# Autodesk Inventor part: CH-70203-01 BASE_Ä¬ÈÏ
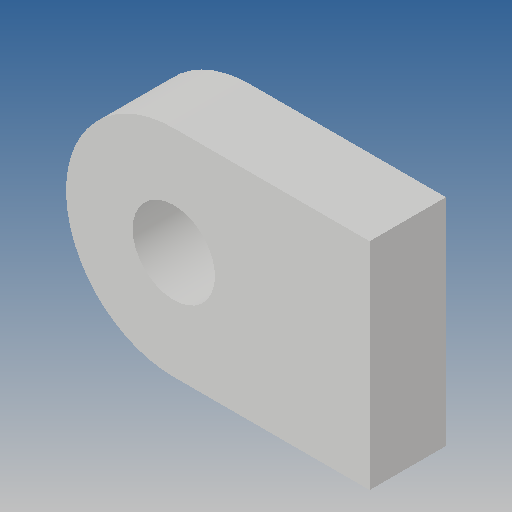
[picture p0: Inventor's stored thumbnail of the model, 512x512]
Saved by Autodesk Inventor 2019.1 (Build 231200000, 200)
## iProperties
Created: 2010-06
Part Number: CH-70203-01 BASE_Ä¬ÈÏ
Material: Ogólny
Document SubType Name: Modeling
Designer: CADENGINEERING4
Density: 1 g/cm^3
Appearance: Domyślna
Author: CADENGINEERING4
Revision Number: ÈÎºÎ
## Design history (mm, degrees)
feature "NONE"
node "Bryła1"
